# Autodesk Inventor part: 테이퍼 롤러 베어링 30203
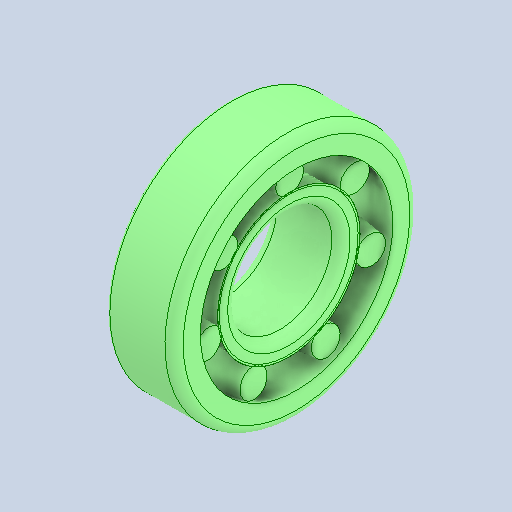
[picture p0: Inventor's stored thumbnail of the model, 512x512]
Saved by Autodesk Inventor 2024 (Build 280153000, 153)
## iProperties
Created: 2026-01
Part Number: 테이퍼 롤러 베어링 30203
Material: 강철, 연강
Description: 테이퍼 롤러 베어링
Document SubType Name: Modeling
Designer: 2-10
Density: 7.85 g/cm^3
Appearance: 기본값
Author: jhkim
Sending System: Autodesk Inventor 2026
Preprocessor: ST-DEVELOPER v20.1
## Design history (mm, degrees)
node "테이퍼 롤러 베어링 302031"
node "솔리드1"
node "솔리드2"
body "Solid1"
node "Solid1:1"
